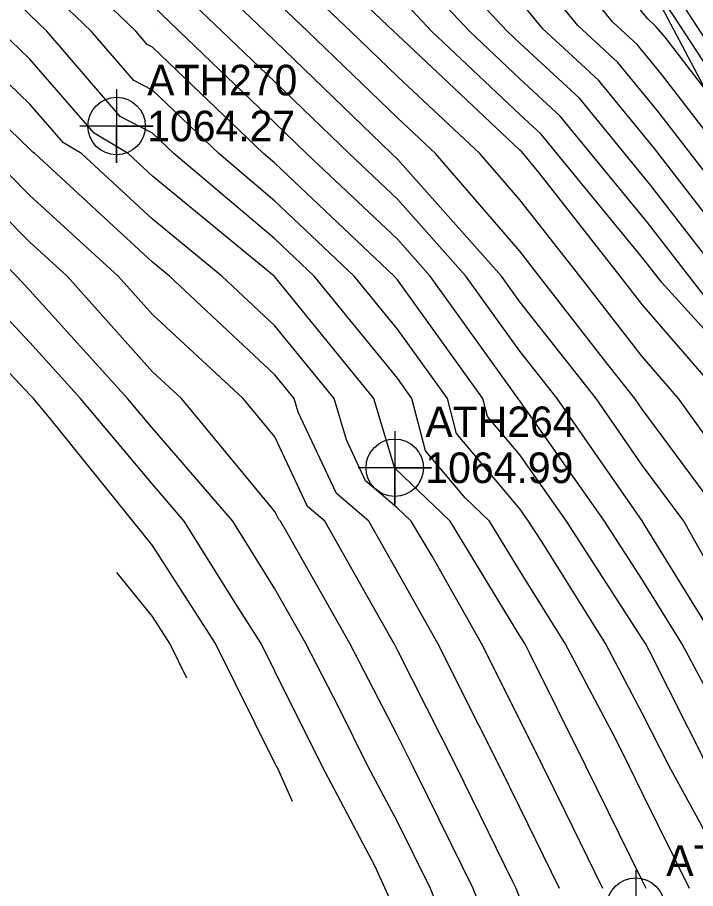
# Model space of a CAD drawing. Extents: x 1213164 to 1213550, y 766120 to 766870.
# Drawn here: x 1213299 to 1213354.4, y 766180 to 766251.1 of the extents above; entities that cross this region are included whole.
import ezdxf

# ---------------------------------------------------------------- set-up
doc = ezdxf.new("R2010")
doc.units = 0
for name, color, linetype in [('Default', 7, 'Continuous'), ('Exist DTM Breakline', 7, 'Continuous'), ('Exist DTM QL2 LIDAR Elevation Point', 7, 'Continuous'), ('Exist DTM Regular Point CELL', 7, 'Continuous'), ('Exist DTM Regular Point Cogo Elevation', 7, 'Continuous'), ('Exist DTM Regular Point Cogo Number', 7, 'Continuous')]:
    doc.layers.add(name, color=color, linetype=linetype)

msp = doc.modelspace()

# ---------------------------------------------------------------- linework, layer by layer
at = {"layer": 'Default'}
for points in [[(1213398.302, 766167.273), (1213391.311, 766182.637), (1213389.385, 766185.967), (1213387.683, 766188.383), (1213386.252, 766192.632), (1213386.005, 766193.808), (1213370.637, 766217.273), (1213370.354, 766217.731), (1213370.211, 766218.048), (1213365.866, 766224.633), (1213365.644, 766224.878), (1213351.286, 766243.455), (1213348.011, 766247.447), (1213344.739, 766250.464), (1213339.508, 766256.882), (1213332.176, 766264.77), (1213330, 766266.585), (1213326.141, 766270), (1213320, 766275.819), (1213315.808, 766280), (1213310, 766288.059), (1213308.8, 766290), (1213300, 766299.975)], [(1213406.02, 766158.464), (1213404.75, 766161.749), (1213403.991, 766165.405), (1213397.264, 766180.187), (1213392.665, 766187.956), (1213389.386, 766193.496), (1213388.09, 766195.563), (1213372.837, 766218.365), (1213372.177, 766219.418), (1213368.044, 766225.598), (1213366.489, 766227.932), (1213355.2, 766245.181), (1213351.863, 766249.498), (1213351.151, 766250.366), (1213350.44, 766251.022), (1213338.916, 766265.161), (1213334.514, 766269.897), (1213332.057, 766271.947), (1213324.144, 766279.448), (1213322.274, 766281.511), (1213320, 766284.171), (1213315.656, 766290), (1213310, 766297.408)], [(1213390.862, 766178.307), (1213387.226, 766184.594), (1213384.013, 766189.155), (1213383.265, 766191.375), (1213382.468, 766195.177), (1213370.497, 766213.456), (1213368.64, 766216.451), (1213367.706, 766218.527), (1213364.427, 766223.497), (1213362.131, 766226.028), (1213350.997, 766240.434), (1213346.441, 766245.987), (1213341.888, 766250.185), (1213339.804, 766252.742), (1213331.006, 766262.206), (1213330, 766263.046), (1213322.142, 766270), (1213320, 766272.029), (1213312.007, 766280), (1213310, 766282.786), (1213305.54, 766290), (1213300, 766296.279)], [(1213407.843, 766161.026), (1213407.212, 766162.657), (1213406.836, 766164.47), (1213403.498, 766171.806), (1213393.637, 766188.464), (1213390.543, 766193.69), (1213388.413, 766197.088), (1213374.031, 766218.586), (1213373.009, 766220.218), (1213369.114, 766226.043), (1213366.736, 766229.611), (1213352.496, 766251.369), (1213352.321, 766251.632), (1213349.484, 766255.972), (1213338.62, 766269.301), (1213335.684, 766272.46), (1213334.044, 766273.828), (1213328.765, 766278.832), (1213324.81, 766283.196), (1213320, 766288.821), (1213319.121, 766290), (1213316.285, 766293.715)], [(1213390.412, 766173.977), (1213385.067, 766183.221), (1213380.343, 766189.928), (1213380.279, 766190.117), (1213378.931, 766196.545), (1213370.356, 766209.638), (1213366.926, 766215.172), (1213365.202, 766219.006), (1213362.988, 766222.36), (1213358.618, 766227.178), (1213350.708, 766237.412), (1213344.871, 766244.528), (1213340, 766249.019), (1213338.96, 766250), (1213330, 766259.543), (1213329.52, 766260), (1213320, 766268.56), (1213318.317, 766270), (1213310, 766278.295), (1213308.789, 766279.733), (1213308.647, 766280), (1213305.97, 766284.03), (1213302.279, 766290), (1213300, 766292.583)], [(1213401.147, 766166.339), (1213391.76, 766186.967), (1213391.544, 766187.34), (1213391.354, 766187.61), (1213391.031, 766188.569), (1213388.229, 766193.302), (1213387.768, 766194.037), (1213371.642, 766218.143), (1213371.345, 766218.618), (1213366.975, 766225.153), (1213366.241, 766226.254), (1213360.916, 766234.391), (1213351.575, 766246.477), (1213349.581, 766248.906), (1213347.589, 766250.743), (1213339.212, 766261.022), (1213333.345, 766267.333), (1213330.07, 766270.066), (1213327.457, 766272.543), (1213320, 766279.609), (1213319.608, 766280), (1213318.596, 766281.404), (1213312.19, 766290), (1213310, 766292.869)], [(1213409.657, 766163.556), (1213409.651, 766163.558), (1213409.638, 766163.582), (1213394.609, 766188.972), (1213391.701, 766193.885), (1213388.735, 766198.614), (1213375.226, 766218.808), (1213373.841, 766221.018), (1213370.183, 766226.488), (1213366.984, 766231.289), (1213353.558, 766251.803), (1213352.99, 766252.657), (1213343.768, 766266.762), (1213338.325, 766273.441), (1213336.853, 766275.024), (1213336.032, 766275.709), (1213333.386, 766278.217), (1213327.346, 766284.882), (1213323.381, 766289.519), (1213319.491, 766293.189)], [(1213382.907, 766181.848), (1213380, 766185.976), (1213377.686, 766190), (1213376.271, 766193.729), (1213375.394, 766197.913), (1213370.215, 766205.821), (1213365.212, 766213.892), (1213362.697, 766219.484), (1213361.55, 766221.224), (1213355.105, 766228.329), (1213350.42, 766234.391), (1213343.301, 766243.069), (1213340, 766246.112), (1213335.881, 766250), (1213330, 766256.264), (1213326.072, 766260), (1213320, 766265.46), (1213314.693, 766270), (1213310, 766274.68), (1213306.222, 766279.168), (1213305.779, 766280), (1213300, 766288.7), (1213299.426, 766289.426), (1213298.823, 766290)], [(1213382.426, 766177.574), (1213380.748, 766180.476), (1213380, 766181.538), (1213375.134, 766190), (1213372.158, 766197.842), (1213371.856, 766199.282), (1213370.074, 766202.003), (1213363.498, 766212.612), (1213360.193, 766219.963), (1213360.111, 766220.088), (1213351.592, 766229.479), (1213350.131, 766231.369), (1213341.731, 766241.609), (1213340, 766243.205), (1213332.802, 766250), (1213330, 766252.985), (1213322.625, 766260), (1213320, 766262.36), (1213311.069, 766270), (1213310, 766271.066), (1213303.654, 766278.603), (1213302.911, 766280), (1213300, 766284.383), (1213297.518, 766287.518)], [(1213375.448, 766180), (1213370.07, 766189.93), (1213370.03, 766190), (1213370, 766190.078), (1213365.361, 766200), (1213360.272, 766209.728), (1213360.071, 766210.053), (1213360, 766210.21), (1213352.969, 766220), (1213350, 766223.443), (1213344.895, 766230), (1213340, 766236.23), (1213336.75, 766240), (1213330, 766246.311), (1213326.179, 766250), (1213320, 766255.873), (1213315.679, 766260), (1213310, 766264.885), (1213304.642, 766270), (1213300.643, 766274.799), (1213299.076, 766276.583), (1213297.321, 766278.701)], [(1213372.694, 766180), (1213370, 766184.975), (1213367.184, 766190), (1213364.163, 766195.837), (1213362.216, 766200), (1213360, 766204.237), (1213356.762, 766210), (1213350, 766219.142), (1213349.403, 766220), (1213347.2, 766222.8), (1213341.594, 766230), (1213340, 766232.029), (1213333.13, 766240), (1213330, 766242.926), (1213322.674, 766250), (1213320, 766252.541), (1213312.191, 766260), (1213310, 766261.884), (1213301.499, 766270), (1213300.208, 766271.55), (1213297.067, 766275.126)], [(1213363.857, 766180), (1213360, 766187.265), (1213358.494, 766190), (1213356.952, 766193.048), (1213353.22, 766200), (1213350, 766205.222), (1213346.909, 766210), (1213340, 766219.818), (1213339.895, 766219.942), (1213339.88, 766220), (1213339.57, 766220.43), (1213332.681, 766230), (1213330, 766233.015), (1213322.591, 766240), (1213320, 766242.503), (1213312.179, 766250), (1213310, 766252.081), (1213301.814, 766260), (1213300, 766261.724), (1213291.701, 766270)], [(1213366.896, 766180), (1213363.383, 766186.617), (1213361.487, 766190), (1213360, 766192.873), (1213356.174, 766200), (1213350.02, 766209.98), (1213350.009, 766210), (1213350, 766210.012), (1213343.047, 766220), (1213340, 766223.872), (1213335.589, 766230), (1213330, 766236.286), (1213326.061, 766240), (1213320, 766245.854), (1213315.675, 766250), (1213310, 766255.42), (1213305.265, 766260), (1213300, 766265.004), (1213294.99, 766270)], [(1213369.935, 766180), (1213369.861, 766180.139), (1213364.336, 766190), (1213360, 766198.376), (1213359.128, 766200), (1213357.725, 766202.275), (1213353.386, 766210), (1213350, 766214.577), (1213346.225, 766220), (1213340, 766227.912), (1213338.497, 766230), (1213330, 766239.557), (1213329.53, 766240), (1213320, 766249.205), (1213319.17, 766250), (1213310, 766258.758), (1213308.717, 766260), (1213300, 766268.285), (1213298.28, 766270)], [(1213353.87, 766180), (1213350, 766187.817), (1213348.926, 766190), (1213347.863, 766192.137), (1213343.701, 766200), (1213340, 766205.93), (1213337.531, 766210), (1213335.539, 766211.903), (1213332.302, 766215.745), (1213331.196, 766220), (1213330, 766221.658), (1213323.221, 766230), (1213320, 766233.047), (1213311.748, 766240), (1213310, 766241.672), (1213307.369, 766243.044), (1213301.366, 766250), (1213300, 766251.319), (1213291.135, 766260)], [(1213357.412, 766180), (1213354.875, 766185.125), (1213352.19, 766190), (1213350, 766194.33), (1213346.999, 766200), (1213342.014, 766207.986), (1213340.711, 766210), (1213340, 766211.011), (1213334.833, 766217.144), (1213334.09, 766220), (1213330, 766225.672), (1213326.483, 766230), (1213320, 766236.133), (1213315.41, 766240), (1213310, 766245.176), (1213308.476, 766245.971), (1213304.999, 766250), (1213300, 766254.828), (1213294.718, 766260)], [(1213360.819, 766180), (1213360, 766181.542), (1213355.342, 766190), (1213350.574, 766199.426), (1213350.266, 766200), (1213350, 766200.431), (1213343.81, 766210), (1213340, 766215.414), (1213337.364, 766218.543), (1213336.985, 766220), (1213330, 766229.687), (1213329.746, 766230), (1213320, 766239.219), (1213319.073, 766240), (1213310, 766248.68), (1213309.583, 766248.898), (1213308.632, 766250), (1213300, 766258.336), (1213298.301, 766260)], [(1213378.201, 766180), (1213376.075, 766183.925), (1213372.582, 766190), (1213370, 766196.804), (1213368.506, 766200), (1213366.866, 766203.134), (1213361.784, 766211.332), (1213360, 766215.301), (1213356.625, 766220), (1213350, 766227.682), (1213348.195, 766230), (1213341.579, 766238.421), (1213340.161, 766240.15), (1213340, 766240.298), (1213334.673, 766245.327), (1213330, 766249.696), (1213329.685, 766250), (1213320, 766259.205)], [(1213343.237, 766180), (1213340, 766186.622), (1213338.35, 766190), (1213336.651, 766193.349), (1213333.301, 766200), (1213330, 766205.874), (1213327.663, 766210), (1213325.041, 766212.243), (1213321.908, 766218.9), (1213321.582, 766220), (1213320, 766221.945), (1213311.397, 766230), (1213310, 766231.147), (1213300.386, 766240), (1213300.253, 766240.081), (1213300, 766240.371), (1213290.02, 766249.98)], [(1213346.782, 766180), (1213343.705, 766186.295), (1213341.882, 766190), (1213340, 766193.784), (1213336.869, 766200), (1213332.851, 766207.149), (1213331.122, 766210), (1213329.946, 766211.124), (1213327.407, 766213.296), (1213325.835, 766216.636), (1213324.836, 766220), (1213320, 766225.947), (1213315.671, 766230), (1213310, 766234.656), (1213304.196, 766240), (1213302.75, 766240.877), (1213300, 766244.041), (1213293.811, 766250)], [(1213350.327, 766180), (1213350, 766180.661), (1213345.404, 766190), (1213340.858, 766199.142), (1213340.404, 766200), (1213340, 766200.647), (1213334.326, 766210), (1213329.79, 766214.334), (1213329.772, 766214.349), (1213329.762, 766214.372), (1213328.09, 766220), (1213320, 766229.949), (1213319.946, 766230), (1213310, 766238.165), (1213308.007, 766240), (1213305.247, 766241.673), (1213300, 766247.71), (1213297.622, 766250)], [(1213339.53, 766160.47), (1213336.576, 766170), (1213334.502, 766175.498), (1213332.697, 766180), (1213330, 766185.456), (1213327.599, 766190), (1213325.224, 766194.776), (1213322.529, 766200), (1213320, 766204.469), (1213316.56, 766210), (1213310, 766217.583), (1213307.97, 766220), (1213300, 766228.836), (1213298.907, 766230), (1213290, 766238.953), (1213281.786, 766246.427)], [(1213346.79, 766146.419), (1213344.171, 766155.829), (1213343.094, 766160), (1213340.28, 766169.72), (1213340.212, 766170), (1213340.127, 766170.114), (1213340, 766170.512), (1213336.197, 766180), (1213332.478, 766187.522), (1213331.268, 766190), (1213330, 766192.499), (1213326.13, 766200), (1213321.087, 766208.913), (1213320.471, 766210), (1213320.31, 766210.138), (1213320, 766210.797), (1213312.376, 766220), (1213310, 766222.2), (1213303.029, 766230), (1213300, 766232.768), (1213292.803, 766240)], [(1213352.882, 766134.236), (1213352.536, 766137.464), (1213351.878, 766140), (1213350, 766146.763), (1213348.751, 766151.249), (1213346.492, 766160), (1213345.062, 766164.938), (1213343.833, 766170), (1213342.289, 766172.066), (1213340, 766179.241), (1213339.696, 766180), (1213339.399, 766180.601), (1213334.809, 766190), (1213330, 766199.478), (1213329.731, 766200), (1213329.38, 766200.62), (1213324.067, 766210), (1213322.676, 766211.191), (1213320, 766216.876), (1213317.412, 766220), (1213310, 766226.862), (1213307.195, 766230), (1213300, 766236.577), (1213296.593, 766240)], [(1213334.26, 766165.74), (1213332.94, 766170), (1213330, 766177.791), (1213328.183, 766181.817), (1213323.86, 766190), (1213320, 766197.761), (1213318.888, 766200), (1213316.882, 766203.118), (1213312.602, 766210), (1213310, 766213.007), (1213304.125, 766220), (1213300, 766224.574), (1213294.905, 766230), (1213290, 766234.93), (1213285.477, 766239.047)], [(1213321.439, 766187.122), (1213320.255, 766189.745), (1213320.12, 766190), (1213320, 766190.242), (1213315.152, 766200), (1213310, 766208.01), (1213301.758, 766218.242), (1213300.281, 766220), (1213300, 766220.312), (1213290.904, 766230), (1213290, 766230.908), (1213289.167, 766231.666)], [(1213312.816, 766197.184), (1213311.417, 766200), (1213310, 766202.203), (1213307.096, 766205.809)]]:
    msp.add_lwpolyline(points, dxfattribs=at)
at = {"layer": 'Exist DTM Breakline'}
msp.add_lwpolyline([(1213409.638, 766163.55), (1213387.59, 766193.195), (1213366.02, 766224.755), (1213332.393, 766288.235), (1213308.213, 766325.957), (1213302.167, 766339.076)], dxfattribs=at)
at = {"layer": 'Exist DTM QL2 LIDAR Elevation Point'}
for p, q in [((1213300, 766250), (1213300, 766250)), ((1213310, 766250), (1213310, 766250)), ((1213320, 766250), (1213320, 766250)), ((1213330, 766250), (1213330, 766250)), ((1213340, 766250), (1213340, 766250)), ((1213300, 766240), (1213300, 766240)), ((1213310, 766240), (1213310, 766240)), ((1213320, 766240), (1213320, 766240)), ((1213330, 766240), (1213330, 766240)), ((1213340, 766240), (1213340, 766240)), ((1213300, 766230), (1213300, 766230)), ((1213310, 766230), (1213310, 766230)), ((1213320, 766230), (1213320, 766230)), ((1213330, 766230), (1213330, 766230)), ((1213340, 766230), (1213340, 766230)), ((1213350, 766230), (1213350, 766230)), ((1213300, 766220), (1213300, 766220)), ((1213310, 766220), (1213310, 766220)), ((1213320, 766220), (1213320, 766220)), ((1213330, 766220), (1213330, 766220)), ((1213340, 766220), (1213340, 766220)), ((1213350, 766220), (1213350, 766220)), ((1213310, 766210), (1213310, 766210)), ((1213320, 766210), (1213320, 766210)), ((1213330, 766210), (1213330, 766210)), ((1213340, 766210), (1213340, 766210)), ((1213350, 766210), (1213350, 766210)), ((1213310, 766200), (1213310, 766200)), ((1213320, 766200), (1213320, 766200)), ((1213330, 766200), (1213330, 766200)), ((1213340, 766200), (1213340, 766200)), ((1213350, 766200), (1213350, 766200)), ((1213320, 766190), (1213320, 766190)), ((1213330, 766190), (1213330, 766190)), ((1213340, 766190), (1213340, 766190)), ((1213350, 766190), (1213350, 766190))]:
    msp.add_line(p, q, dxfattribs=at)
at = {"layer": 'Exist DTM Regular Point CELL'}
for points in [[(1213307.07, 766245.254), (1213307.07, 766239.254), (1213307.07, 766242.254), (1213310.07, 766242.254), (1213304.07, 766242.254)], [(1213329.789, 766217.356), (1213329.789, 766211.356), (1213329.789, 766214.356), (1213332.789, 766214.356), (1213326.789, 766214.356)], [(1213349.465, 766181.542), (1213349.465, 766175.542), (1213349.465, 766178.542), (1213352.465, 766178.542), (1213346.465, 766178.542)]]:
    msp.add_lwpolyline(points, dxfattribs=at)
for centre in [(1213307.07, 766242.254), (1213329.789, 766214.356), (1213349.465, 766178.542)]:
    msp.add_circle(centre, 2.344, dxfattribs=at)

# ---------------------------------------------------------------- texts
at = {"layer": 'Exist DTM Regular Point Cogo Elevation'}
for s, p in [('1064.27', (1213309.57, 766241.004)), ('1064.99', (1213332.289, 766213.106))]:
    msp.add_text(s, height=2.5, dxfattribs=at).set_placement(p)
at = {"layer": 'Exist DTM Regular Point Cogo Number'}
for s, p in [('ATH270', (1213309.57, 766244.754)), ('ATH264', (1213332.289, 766216.856)), ('ATH263', (1213351.965, 766181.042))]:
    msp.add_text(s, height=2.5, dxfattribs=at).set_placement(p)

doc.saveas('drawing.dxf')
